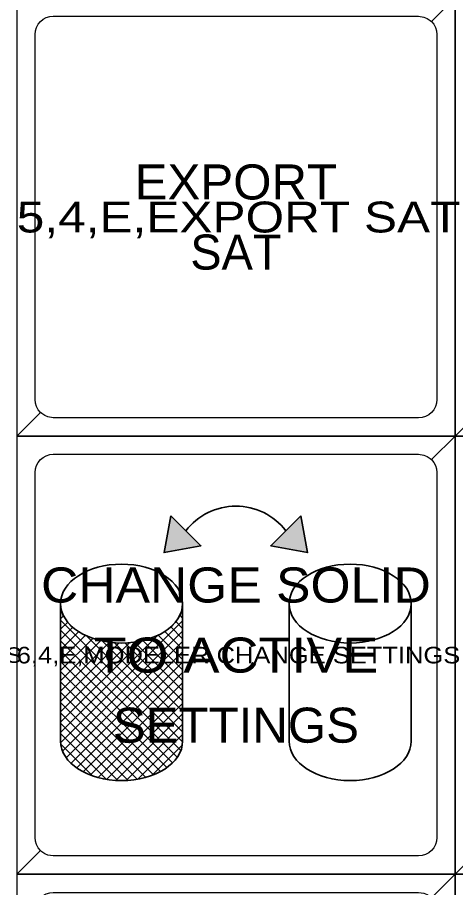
# Model space of a CAD drawing. Extents: x 95909.2 to 95923.3, y 90965 to 90971.2.
# Drawn here: x 95911.588 to 95912.188, y 90967.542 to 90968.734 of the extents above; entities that cross this region are included whole.
import ezdxf
from ezdxf.enums import TextEntityAlignment as Align

# ---------------------------------------------------------------- set-up
doc = ezdxf.new("R2010")
doc.units = 0
doc.header["$LTSCALE"] = 0.019
for name, color, linetype, lineweight in [('1', 7, 'Continuous', 25), ('2', 7, 'Continuous', 25), ('3', 7, 'Continuous', 25), ('4', 7, 'Continuous', 25), ('6', 7, 'Continuous', 13)]:
    doc.layers.add(name, color=color, linetype=linetype, lineweight=lineweight)
for name, color, linetype in [('5', 7, 'Continuous'), ('63', 7, 'Continuous'), ('9', 7, 'Continuous')]:
    doc.layers.add(name, color=color, linetype=linetype)

msp = doc.modelspace()

# ---------------------------------------------------------------- hatches: boundary and pattern name
at = {"layer": '6'}
for points in [[(95911.7977, 90968.0511), (95911.7884, 90968.0006), (95911.8389, 90968.0101)], [(95911.9759, 90968.0511), (95911.985, 90968.0006), (95911.9346, 90968.0101)]]:
    msp.add_hatch(color=256, dxfattribs=at).paths.add_polyline_path(points)

# ---------------------------------------------------------------- linework, layer by layer
at = {"layer": '1'}
for points in [[(95911.5868, 90968.1603), (95912.1868, 90968.1603), (95912.1868, 90968.7603), (95911.5868, 90968.7603)], [(95912.1868, 90968.1603), (95912.7868, 90968.1603), (95912.7868, 90968.7603), (95912.1868, 90968.7603)], [(95911.5868, 90967.5603), (95912.1868, 90967.5603), (95912.1868, 90968.1603), (95911.5868, 90968.1603)], [(95912.1868, 90967.5603), (95912.7868, 90967.5603), (95912.7868, 90968.1603), (95912.1868, 90968.1603)], [(95911.5868, 90966.9603), (95912.1868, 90966.9603), (95912.1868, 90967.5603), (95911.5868, 90967.5603)], [(95912.1868, 90966.9603), (95912.7868, 90966.9603), (95912.7868, 90967.5603), (95912.1868, 90967.5603)]]:
    msp.add_lwpolyline(points, close=True, dxfattribs=at)
at = {"layer": '2'}
for points in [[(95911.5868, 90968.1603), (95912.1868, 90968.1603), (95912.1868, 90968.7603), (95911.5868, 90968.7603)], [(95912.1868, 90968.1603), (95912.7868, 90968.1603), (95912.7868, 90968.7603), (95912.1868, 90968.7603)], [(95911.5868, 90967.5603), (95912.1868, 90967.5603), (95912.1868, 90968.1603), (95911.5868, 90968.1603)], [(95912.1868, 90967.5603), (95912.7868, 90967.5603), (95912.7868, 90968.1603), (95912.1868, 90968.1603)], [(95911.5868, 90966.9603), (95912.1868, 90966.9603), (95912.1868, 90967.5603), (95911.5868, 90967.5603)], [(95912.1868, 90966.9603), (95912.7868, 90966.9603), (95912.7868, 90967.5603), (95912.1868, 90967.5603)]]:
    msp.add_lwpolyline(points, close=True, dxfattribs=at)
at = {"layer": '3'}
for points in [[(95912.1868, 90968.7603), (95911.5868, 90968.7603), (95911.5868, 90968.1603), (95911.6191, 90968.1926), (95911.616, 90968.1964), (95911.6137, 90968.2007), (95911.6123, 90968.2054), (95911.6118, 90968.2103), (95911.6118, 90968.7103), (95911.6123, 90968.7152), (95911.6137, 90968.7199), (95911.616, 90968.7242), (95911.6191, 90968.728), (95911.6191, 90968.728), (95911.6229, 90968.7311), (95911.6272, 90968.7334), (95911.6319, 90968.7348), (95911.6368, 90968.7353), (95912.1368, 90968.7353), (95912.1441, 90968.7342), (95912.1486, 90968.7323), (95912.1527, 90968.7296), (95912.1545, 90968.728)], [(95912.7868, 90968.7603), (95912.1868, 90968.7603), (95912.1868, 90968.1603), (95912.2191, 90968.1926), (95912.216, 90968.1964), (95912.2137, 90968.2007), (95912.2123, 90968.2054), (95912.2118, 90968.2103), (95912.2118, 90968.7103), (95912.2123, 90968.7152), (95912.2137, 90968.7199), (95912.216, 90968.7242), (95912.2191, 90968.728), (95912.2191, 90968.728), (95912.2229, 90968.7311), (95912.2272, 90968.7334), (95912.2319, 90968.7348), (95912.2368, 90968.7353), (95912.7368, 90968.7353), (95912.7441, 90968.7342), (95912.7486, 90968.7323), (95912.7527, 90968.7296), (95912.7545, 90968.728)], [(95912.1868, 90968.1603), (95911.5868, 90968.1603), (95911.5868, 90967.5603), (95911.6191, 90967.5926), (95911.616, 90967.5964), (95911.6137, 90967.6007), (95911.6123, 90967.6054), (95911.6118, 90967.6103), (95911.6118, 90968.1103), (95911.6123, 90968.1152), (95911.6137, 90968.1199), (95911.616, 90968.1242), (95911.6191, 90968.128), (95911.6191, 90968.128), (95911.6229, 90968.1311), (95911.6272, 90968.1334), (95911.6319, 90968.1348), (95911.6368, 90968.1353), (95912.1368, 90968.1353), (95912.1441, 90968.1342), (95912.1486, 90968.1323), (95912.1527, 90968.1296), (95912.1545, 90968.128)], [(95912.7868, 90968.1603), (95912.1868, 90968.1603), (95912.1868, 90967.5603), (95912.2191, 90967.5926), (95912.216, 90967.5964), (95912.2137, 90967.6007), (95912.2123, 90967.6054), (95912.2118, 90967.6103), (95912.2118, 90968.1103), (95912.2123, 90968.1152), (95912.2137, 90968.1199), (95912.216, 90968.1242), (95912.2191, 90968.128), (95912.2191, 90968.128), (95912.2229, 90968.1311), (95912.2272, 90968.1334), (95912.2319, 90968.1348), (95912.2368, 90968.1353), (95912.7368, 90968.1353), (95912.7441, 90968.1342), (95912.7486, 90968.1323), (95912.7527, 90968.1296), (95912.7545, 90968.128)], [(95912.1868, 90967.5603), (95911.5868, 90967.5603), (95911.5868, 90966.9603), (95911.6191, 90966.9926), (95911.616, 90966.9964), (95911.6137, 90967.0007), (95911.6123, 90967.0054), (95911.6118, 90967.0103), (95911.6118, 90967.5103), (95911.6123, 90967.5152), (95911.6137, 90967.5199), (95911.616, 90967.5242), (95911.6191, 90967.528), (95911.6191, 90967.528), (95911.6229, 90967.5311), (95911.6272, 90967.5334), (95911.6319, 90967.5348), (95911.6368, 90967.5353), (95912.1368, 90967.5353), (95912.1441, 90967.5342), (95912.1486, 90967.5323), (95912.1527, 90967.5296), (95912.1545, 90967.528)], [(95912.7868, 90967.5603), (95912.1868, 90967.5603), (95912.1868, 90966.9603), (95912.2191, 90966.9926), (95912.216, 90966.9964), (95912.2137, 90967.0007), (95912.2123, 90967.0054), (95912.2118, 90967.0103), (95912.2118, 90967.5103), (95912.2123, 90967.5152), (95912.2137, 90967.5199), (95912.216, 90967.5242), (95912.2191, 90967.528), (95912.2191, 90967.528), (95912.2229, 90967.5311), (95912.2272, 90967.5334), (95912.2319, 90967.5348), (95912.2368, 90967.5353), (95912.7368, 90967.5353), (95912.7441, 90967.5342), (95912.7486, 90967.5323), (95912.7527, 90967.5296), (95912.7545, 90967.528)]]:
    msp.add_lwpolyline(points, close=True, dxfattribs=at)
at = {"layer": '4'}
for points in [[(95911.5868, 90968.1603), (95912.1868, 90968.1603), (95912.1868, 90968.7603), (95912.1545, 90968.728), (95912.1576, 90968.7242), (95912.1599, 90968.7199), (95912.1613, 90968.7152), (95912.1618, 90968.7103), (95912.1618, 90968.2103), (95912.1613, 90968.2054), (95912.1599, 90968.2007), (95912.1576, 90968.1964), (95912.1545, 90968.1926), (95912.1545, 90968.1926), (95912.1507, 90968.1895), (95912.1464, 90968.1872), (95912.1417, 90968.1858), (95912.1368, 90968.1853), (95911.6368, 90968.1853), (95911.6295, 90968.1864), (95911.625, 90968.1883), (95911.6209, 90968.191), (95911.6191, 90968.1926)], [(95912.1868, 90968.1603), (95912.7868, 90968.1603), (95912.7868, 90968.7603), (95912.7545, 90968.728), (95912.7576, 90968.7242), (95912.7599, 90968.7199), (95912.7613, 90968.7152), (95912.7618, 90968.7103), (95912.7618, 90968.2103), (95912.7613, 90968.2054), (95912.7599, 90968.2007), (95912.7576, 90968.1964), (95912.7545, 90968.1926), (95912.7545, 90968.1926), (95912.7507, 90968.1895), (95912.7464, 90968.1872), (95912.7417, 90968.1858), (95912.7368, 90968.1853), (95912.2368, 90968.1853), (95912.2295, 90968.1864), (95912.225, 90968.1883), (95912.2209, 90968.191), (95912.2191, 90968.1926)], [(95911.5868, 90967.5603), (95912.1868, 90967.5603), (95912.1868, 90968.1603), (95912.1545, 90968.128), (95912.1576, 90968.1242), (95912.1599, 90968.1199), (95912.1613, 90968.1152), (95912.1618, 90968.1103), (95912.1618, 90967.6103), (95912.1613, 90967.6054), (95912.1599, 90967.6007), (95912.1576, 90967.5964), (95912.1545, 90967.5926), (95912.1545, 90967.5926), (95912.1507, 90967.5895), (95912.1464, 90967.5872), (95912.1417, 90967.5858), (95912.1368, 90967.5853), (95911.6368, 90967.5853), (95911.6295, 90967.5864), (95911.625, 90967.5883), (95911.6209, 90967.591), (95911.6191, 90967.5926)], [(95912.1868, 90967.5603), (95912.7868, 90967.5603), (95912.7868, 90968.1603), (95912.7545, 90968.128), (95912.7576, 90968.1242), (95912.7599, 90968.1199), (95912.7613, 90968.1152), (95912.7618, 90968.1103), (95912.7618, 90967.6103), (95912.7613, 90967.6054), (95912.7599, 90967.6007), (95912.7576, 90967.5964), (95912.7545, 90967.5926), (95912.7545, 90967.5926), (95912.7507, 90967.5895), (95912.7464, 90967.5872), (95912.7417, 90967.5858), (95912.7368, 90967.5853), (95912.2368, 90967.5853), (95912.2295, 90967.5864), (95912.225, 90967.5883), (95912.2209, 90967.591), (95912.2191, 90967.5926)], [(95911.5868, 90966.9603), (95912.1868, 90966.9603), (95912.1868, 90967.5603), (95912.1545, 90967.528), (95912.1576, 90967.5242), (95912.1599, 90967.5199), (95912.1613, 90967.5152), (95912.1618, 90967.5103), (95912.1618, 90967.0103), (95912.1613, 90967.0054), (95912.1599, 90967.0007), (95912.1576, 90966.9964), (95912.1545, 90966.9926), (95912.1545, 90966.9926), (95912.1507, 90966.9895), (95912.1464, 90966.9872), (95912.1417, 90966.9858), (95912.1368, 90966.9853), (95911.6368, 90966.9853), (95911.6295, 90966.9864), (95911.625, 90966.9883), (95911.6209, 90966.991), (95911.6191, 90966.9926)]]:
    msp.add_lwpolyline(points, close=True, dxfattribs=at)
at = {"layer": '6', "lineweight": 35}
for p, q in [((95911.6468, 90967.9308), (95911.6468, 90967.7423)), ((95911.9597, 90967.9308), (95911.9597, 90967.7423)), ((95912.1268, 90967.9308), (95912.1268, 90967.7423))]:
    msp.add_line(p, q, dxfattribs=at)
at = {"layer": '6'}
for p, q in [((95911.6468, 90967.9241), (95911.6473, 90967.9246)), ((95911.6468, 90967.9225), (95911.6482, 90967.921)), ((95911.8119, 90967.9194), (95911.8139, 90967.9215)), ((95911.8134, 90967.9255), (95911.8139, 90967.9251)), ((95911.6468, 90967.9099), (95911.6509, 90967.914)), ((95911.6468, 90967.9083), (95911.8138, 90967.7413)), ((95911.6468, 90967.8958), (95911.6565, 90967.9055)), ((95911.6469, 90967.7403), (95911.8139, 90967.9073)), ((95911.8045, 90967.9061), (95911.8139, 90967.8968)), ((95911.81, 90967.9148), (95911.8139, 90967.9109)), ((95911.6468, 90967.8816), (95911.6636, 90967.8984)), ((95911.6468, 90967.8942), (95911.8114, 90967.7296)), ((95911.6468, 90967.8675), (95911.6717, 90967.8924)), ((95911.6495, 90967.7288), (95911.8139, 90967.8932)), ((95911.7896, 90967.8928), (95911.8139, 90967.8685)), ((95911.7976, 90967.8989), (95911.8139, 90967.8826)), ((95911.6468, 90967.7544), (95911.7799, 90967.8875)), ((95911.6468, 90967.8533), (95911.6808, 90967.8874)), ((95911.6468, 90967.8392), (95911.6908, 90967.8832)), ((95911.6468, 90967.8251), (95911.7018, 90967.8801)), ((95911.6468, 90967.7685), (95911.7583, 90967.88)), ((95911.6468, 90967.88), (95911.8065, 90967.7203)), ((95911.6828, 90967.8864), (95911.8139, 90967.7554)), ((95911.7037, 90967.8797), (95911.8139, 90967.7695)), ((95911.7596, 90967.8803), (95911.8139, 90967.8261)), ((95911.7706, 90967.8835), (95911.8139, 90967.8402)), ((95911.7805, 90967.8877), (95911.8139, 90967.8543)), ((95911.6468, 90967.8109), (95911.7138, 90967.8779)), ((95911.6468, 90967.7826), (95911.7415, 90967.8774)), ((95911.6468, 90967.7968), (95911.7269, 90967.8769)), ((95911.6546, 90967.7197), (95911.8139, 90967.879)), ((95911.7203, 90967.8773), (95911.8139, 90967.7836)), ((95911.7347, 90967.877), (95911.8139, 90967.7978)), ((95911.7478, 90967.878), (95911.8139, 90967.8119)), ((95911.6468, 90967.8659), (95911.8, 90967.7127)), ((95911.6611, 90967.7121), (95911.8139, 90967.8649)), ((95911.6468, 90967.8517), (95911.7923, 90967.7062)), ((95911.6689, 90967.7058), (95911.8139, 90967.8507)), ((95911.6468, 90967.8376), (95911.7836, 90967.7008)), ((95911.6777, 90967.7004), (95911.8139, 90967.8366)), ((95911.6468, 90967.8235), (95911.7739, 90967.6963)), ((95911.6875, 90967.696), (95911.8139, 90967.8225)), ((95911.6468, 90967.8093), (95911.7633, 90967.6928)), ((95911.6981, 90967.6925), (95911.8139, 90967.8083)), ((95911.6468, 90967.7952), (95911.7518, 90967.6902)), ((95911.7098, 90967.69), (95911.8139, 90967.7942)), ((95911.6468, 90967.781), (95911.7392, 90967.6887)), ((95911.7224, 90967.6886), (95911.8139, 90967.78)), ((95911.6468, 90967.7669), (95911.7252, 90967.6885)), ((95911.7365, 90967.6885), (95911.8139, 90967.7659)), ((95911.6468, 90967.7527), (95911.7095, 90967.6901)), ((95911.7525, 90967.6903), (95911.8139, 90967.7517)), ((95911.6471, 90967.7384), (95911.6906, 90967.6948)), ((95911.7718, 90967.6955), (95911.8134, 90967.7371))]:
    msp.add_line(p, q, dxfattribs=at)
at = {"layer": '6', "lineweight": 35}
for points in [[(95911.7977, 90968.0511), (95911.7884, 90968.0006), (95911.8389, 90968.0101)], [(95911.9759, 90968.0511), (95911.985, 90968.0006), (95911.9346, 90968.0101)]]:
    msp.add_lwpolyline(points, close=True, dxfattribs=at)
msp.add_lwpolyline([(95911.8139, 90967.7423), (95911.8139, 90967.9308), (95911.8138, 90967.9308)], dxfattribs=at)
msp.add_arc((95911.88676, 90967.97793), 0.08636, 37.59566, 142.40434, dxfattribs=at)
for centre, major_axis in [((95911.73028, 90967.93078), (0.08353, 0)), ((95912.04324, 90967.93078), (-0.08353, 0))]:
    msp.add_ellipse(centre, major_axis=major_axis, ratio=0.64664, dxfattribs=at)
for centre, major_axis, start_param, end_param in [((95911.73028, 90967.93083), (0.08353, 0), 3.1416618, 6.2831028), ((95911.73028, 90967.74233), (0.08353, 0), 3.1416618, 6.2831028), ((95912.04324, 90967.74233), (-0.08353, 0), 0.0000825, 3.1415235)]:
    msp.add_ellipse(centre, major_axis=major_axis, ratio=0.64664, start_param=start_param, end_param=end_param, dxfattribs=at)

# ---------------------------------------------------------------- texts
at = {"layer": '5'}
for s, width, p in [('CHANGE SOLID', 1.1, (95911.88685, 90967.9323)), ('TO ACTIVE', 1.15, (95911.88685, 90967.8363)), ('SETTINGS', 1.05, (95911.8868, 90967.7403))]:
    msp.add_text(s, height=0.048, dxfattribs=dict(at, width=width)).set_placement(p, align=Align.CENTER)
at = {"layer": '63'}
for s, height, width, p in [('5,4,E,EXPORT SAT', 0.0423, 1.2, (95911.5868, 90968.4391)), ('6,3,E,MODELER CHANGE ATTRIBUTES', 0.0212, 1.15, (95910.9868, 90967.8497)), ('6,4,E,MODELER CHANGE SETTINGS', 0.0227, 1.15, (95911.5868, 90967.8489))]:
    msp.add_text(s, height=height, dxfattribs=dict(at, width=width)).set_placement(p)
at = {"layer": '9', "width": 1.05}
msp.add_text('EXPORT', height=0.048, dxfattribs=at).set_placement((95911.8868, 90968.4843), align=Align.CENTER)
at = {"layer": '9'}
msp.add_text('SAT', height=0.048, dxfattribs=at).set_placement((95911.8868, 90968.3883), align=Align.CENTER)

doc.saveas('drawing.dxf')
